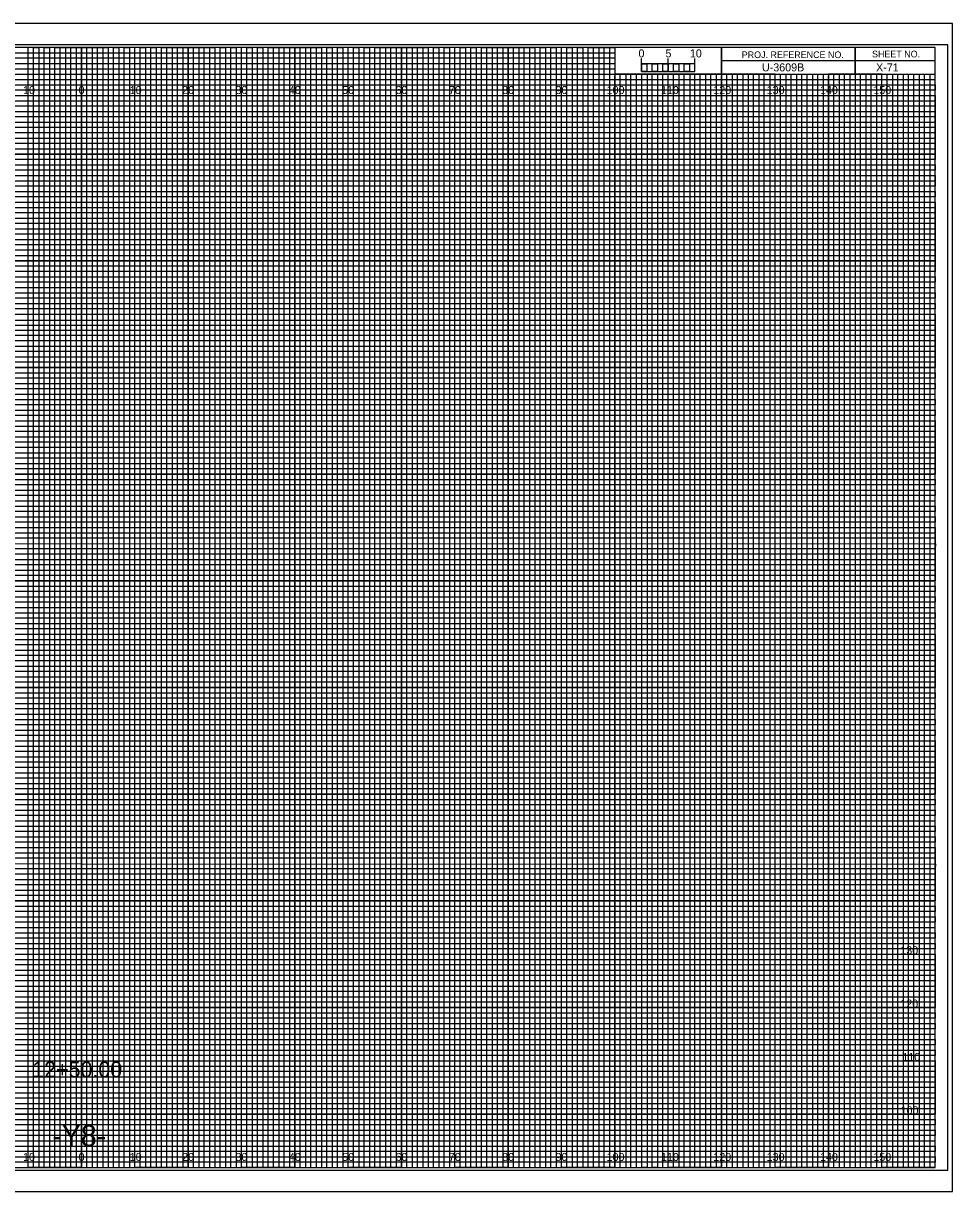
# Model space of a CAD drawing. Extents: x -13 to 323, y -5 to 434.
# Drawn here: x 149.1 to 323.3, y 215.5 to 434.5 of the extents above; entities that cross this region are included whole.
import ezdxf

# ---------------------------------------------------------------- set-up
doc = ezdxf.new("R2010")
doc.units = 0
for name, color, linetype in [('Exist CMT Pavement', 7, 'Continuous'), ('Exist Cross Section Cell', 7, 'Continuous'), ('Exist XS Center Line Elevation Label', 7, 'Continuous'), ('Exist XS Ground Line', 7, 'Continuous'), ('Prop CMT Pvmt Course 1 Wedge', 7, 'Continuous'), ('Prop CMT Pvmt Course 2', 7, 'Continuous'), ('Prop CMT Pvmt Course 2 Wedge', 7, 'Continuous'), ('Prop CMT Pvmt Course 3', 7, 'Continuous'), ('Prop CMT Pvmt Course 3 Wedge', 7, 'Continuous'), ('Prop CMT Pvmt Surface', 7, 'Continuous'), ('Prop CMT Pvmt Wedge Surface 1', 7, 'Continuous'), ('Prop CMT Pvmt Wedge Surface 2', 7, 'Continuous'), ('Prop CMT Shld Paved Course 1', 7, 'Continuous'), ('Prop CMT Shld Paved Course 2', 7, 'Continuous'), ('Prop CMT Shld Paved Course 3', 7, 'Continuous'), ('Prop CMT Subgrade Earthwork', 7, 'Continuous'), ('Scratch_Level_0', 7, 'Continuous')]:
    doc.layers.add(name, color=color, linetype=linetype)

msp = doc.modelspace()

# ---------------------------------------------------------------- linework, layer by layer
at = {"layer": 'Exist XS Center Line Elevation Label'}
for points in [[(145, 220), (155, 220), (155, 430), (165, 430), (165, 220), (175, 220), (175, 430), (185, 430), (185, 220), (195, 220), (195, 430), (205, 430), (205, 220), (215, 220), (215, 430), (225, 430), (225, 220), (235, 220), (235, 430), (245, 430), (245, 220), (255, 220), (255, 430), (259.93, 430), (260, 430), (260, 425), (264.99, 425), (264.99, 220), (275, 220), (275, 425), (285, 425), (285, 220), (295, 220), (295, 425), (305, 425), (305, 220), (315, 220), (315, 425)], [(0, 425), (275, 425)], [(0, 405), (320, 405), (320, 415), (0, 415)], [(0, 385), (320, 385), (320, 395), (0, 395)], [(0, 365), (320, 365), (320, 375), (0, 375)], [(0, 345), (320, 345), (320, 355), (0, 355)], [(0, 325), (320, 325), (320, 335), (0, 335)], [(0, 305), (320, 305), (320, 315), (0, 315)], [(0, 285), (320, 285), (320, 295), (0, 295)], [(0, 265), (320, 265), (320, 275), (0, 275)], [(0, 245), (320, 245), (320, 255), (0, 255)], [(0, 225), (320, 225), (320, 235), (0, 235)]]:
    msp.add_lwpolyline(points, dxfattribs=at)
at = {"layer": 'Exist XS Ground Line'}
for p, q in [((150, 430), (140, 430)), ((150, 220), (150, 430)), ((170, 430), (160, 430)), ((160, 430), (160, 220)), ((170, 220), (170, 430)), ((190, 430), (180, 430)), ((180, 430), (180, 220)), ((190, 220), (190, 430)), ((210, 430), (200, 430)), ((200, 430), (200, 220)), ((210, 220), (210, 430)), ((230, 430), (220, 430)), ((220, 430), (220, 220)), ((230, 220), (230, 430)), ((250, 430), (240, 430)), ((240, 430), (240, 220)), ((250, 220), (250, 430)), ((260, 430), (260, 220)), ((270, 220), (270, 425)), ((290, 425), (280, 425)), ((280, 425), (280, 220)), ((290, 220), (290, 425)), ((310, 425), (300, 425)), ((300, 425), (300, 220)), ((310, 220), (310, 425)), ((160, 220), (150, 220)), ((180, 220), (170, 220)), ((200, 220), (190, 220)), ((220, 220), (210, 220)), ((240, 220), (230, 220)), ((260, 220), (250, 220)), ((280, 220), (270, 220)), ((300, 220), (290, 220)), ((320, 220), (310, 220)), ((320, 220), (320, 220))]:
    msp.add_line(p, q, dxfattribs=at)
for points in [[(0, 420), (320, 420), (320, 410), (0, 410)], [(0, 400), (320, 400), (320, 390), (0, 390)], [(0, 380), (320, 380), (320, 370), (0, 370)], [(0, 360), (320, 360), (320, 350), (0, 350)], [(0, 340), (320, 340), (320, 330), (0, 330)], [(0, 320), (320, 320), (320, 310), (0, 310)], [(0, 300), (320, 300), (320, 290), (0, 290)], [(0, 280), (320, 280), (320, 270), (0, 270)], [(0, 260), (320, 260), (320, 250), (0, 250)], [(0, 240), (320, 240), (320, 230), (0, 230)]]:
    msp.add_lwpolyline(points, dxfattribs=at)
at = {"layer": 'Prop CMT Pvmt Course 1 Wedge'}
for p, q in [((323.3, 434.5), (-13.4, 434.5)), ((-13.4, 215.5), (323.3, 215.5))]:
    msp.add_line(p, q, dxfattribs=at)
at = {"layer": 'Prop CMT Pvmt Course 2'}
msp.add_lwpolyline([(-13.4, 215.5), (323.3, 215.5), (323.3, 434.5), (-13.4, 434.5)], close=True, dxfattribs=at)
at = {"layer": 'Prop CMT Pvmt Course 3'}
msp.add_lwpolyline([(-10.8, 219.5), (322.4, 219.5), (322.4, 430.5), (-10.8, 430.5)], close=True, dxfattribs=at)
at = {"layer": 'Prop CMT Shld Paved Course 1'}
for p, q in [((305, 430), (305, 425)), ((305, 425), (305, 430)), ((280, 427.5), (280, 425)), ((320, 427.49), (280, 427.49)), ((280, 425), (320, 425))]:
    msp.add_line(p, q, dxfattribs=at)
for points in [[(320, 430), (0, 430), (0, 220), (320, 220)], [(280, 430), (260, 430), (260, 425.03), (280, 425.03)], [(320, 430), (280, 430), (280, 425), (320, 425)]]:
    msp.add_lwpolyline(points, close=True, dxfattribs=at)
at = {"layer": 'Prop CMT Shld Paved Course 2'}
for p, q in [((267, 425), (266.01, 425)), ((266.01, 425), (266.01, 220)), ((267, 220), (267, 425)), ((269, 425), (268, 425)), ((268, 425), (268, 220)), ((269, 220), (269, 425)), ((266.01, 220), (265, 220)), ((268, 220), (267, 220))]:
    msp.add_line(p, q, dxfattribs=at)
for points in [[(150, 220), (151, 220), (151, 430), (152, 430), (152, 220)], [(152, 220), (153, 220), (153, 430), (154, 430), (154, 220)], [(155, 220), (156, 220), (156, 430), (157, 430), (157, 220)], [(157, 220), (158, 220), (158, 430), (159, 430), (159, 220)], [(160, 220), (161, 220), (161, 430), (162, 430), (162, 220)], [(162, 220), (163, 220), (163, 430), (164, 430), (164, 220)], [(165, 220), (166, 220), (166, 430), (167, 430), (167, 220)], [(167, 220), (168, 220), (168, 430), (169, 430), (169, 220)], [(170, 220), (171, 220), (171, 430), (172, 430), (172, 220)], [(172, 220), (173, 220), (173, 430), (174, 430), (174, 220)], [(175, 220), (176, 220), (176, 430), (177, 430), (177, 220)], [(177, 220), (178, 220), (178, 430), (179, 430), (179, 220)], [(180, 220), (181, 220), (181, 430), (182, 430), (182, 220)], [(182, 220), (183, 220), (183, 430), (184, 430), (184, 220)], [(185, 220), (186, 220), (186, 430), (187, 430), (187, 220)], [(187, 220), (188, 220), (188, 430), (189, 430), (189, 220)], [(190, 220), (191, 220), (191, 430), (192, 430), (192, 220)], [(192, 220), (193, 220), (193, 430), (194, 430), (194, 220)], [(195, 220), (196, 220), (196, 430), (197, 430), (197, 220)], [(197, 220), (198, 220), (198, 430), (199, 430), (199, 220)], [(200, 220), (201, 220), (201, 430), (202, 430), (202, 220)], [(202, 220), (203, 220), (203, 430), (204, 430), (204, 220)], [(205, 220), (206, 220), (206, 430), (207, 430), (207, 220)], [(207, 220), (208, 220), (208, 430), (209, 430), (209, 220)], [(210, 220), (211, 220), (211, 430), (212, 430), (212, 220)], [(212, 220), (213, 220), (213, 430), (214, 430), (214, 220)], [(215, 220), (216, 220), (216, 430), (217, 430), (217, 220)], [(217, 220), (218, 220), (218, 430), (219, 430), (219, 220)], [(220, 220), (221, 220), (221, 430), (222, 430), (222, 220)], [(222, 220), (223, 220), (223, 430), (224, 430), (224, 220)], [(225, 220), (226, 220), (226, 430), (227, 430), (227, 220)], [(227, 220), (228, 220), (228, 430), (229, 430), (229, 220)], [(230, 220), (231, 220), (231, 430), (232, 430), (232, 220)], [(232, 220), (233, 220), (233, 430), (234, 430), (234, 220)], [(235, 220), (236, 220), (236, 430), (237, 430), (237, 220)], [(237, 220), (238, 220), (238, 430), (239, 430), (239, 220)], [(240, 220), (241, 220), (241, 430), (242, 430), (242, 220)], [(242, 220), (243, 220), (243, 430), (244, 430), (244, 220)], [(245, 220), (246, 220), (246, 430), (247, 430), (247, 220)], [(247, 220), (248, 220), (248, 430), (249, 430), (249, 220)], [(250, 220), (251, 220), (251, 430), (252, 430), (252, 220)], [(252, 220), (253, 220), (253, 430), (254, 430), (254, 220)], [(255, 220), (256, 220), (256, 430), (257, 430), (257, 220)], [(257, 220), (258, 220), (258, 430), (259, 430), (259, 220)], [(260, 220), (261, 220), (261, 425), (262.02, 425), (262.02, 220)], [(262, 220), (263, 220), (263, 425), (263.99, 425), (263.99, 220)], [(270, 220), (270.98, 220), (270.98, 425), (272, 425), (272, 220)], [(272, 220), (273, 220), (273, 425), (274.05, 425), (274.05, 220)], [(275, 220), (276, 220), (276, 425), (277, 425), (277, 220)], [(277, 220), (278, 220), (278, 425), (279, 425), (279, 220)], [(280, 220), (281, 220), (281, 425), (282, 425), (282, 220)], [(282, 220), (283, 220), (283, 425), (284, 425), (284, 220)], [(285, 220), (286, 220), (286, 425), (287, 425), (287, 220)], [(287, 220), (288, 220), (288, 425), (289, 425), (289, 220)], [(290, 220), (291, 220), (291, 425), (292, 425), (292, 220)], [(292, 220), (293, 220), (293, 425), (294, 425), (294, 220)], [(295, 220), (296, 220), (296, 425), (297, 425), (297, 220)], [(297, 220), (298, 220), (298, 425), (299, 425), (299, 220)], [(300, 220), (301, 220), (301, 425), (302, 425), (302, 220)], [(302, 220), (303, 220), (303, 425), (304, 425), (304, 220)], [(305, 220), (306, 220), (306, 425), (307, 425), (307, 220)], [(307, 220), (308, 220), (308, 425), (309, 425), (309, 220)], [(310, 220), (311, 220), (311, 425), (312, 425), (312, 220)], [(312, 220), (313, 220), (313, 425), (314, 425), (314, 220)], [(315, 220), (316, 220), (316, 425), (317, 425), (317, 220)], [(317, 220), (318, 220), (318, 425), (319, 425), (319, 220)]]:
    msp.add_lwpolyline(points, dxfattribs=at)
at = {"layer": 'Prop CMT Shld Paved Course 3'}
for p, q in [((265, 425.49), (265, 427.9)), ((265, 426.9), (265, 427.9)), ((270, 425.49), (270, 427.9)), ((275, 425.49), (275, 427.9)), ((275, 426.9), (275, 427.9))]:
    msp.add_line(p, q, dxfattribs=at)
for points in [[(275, 426.9), (265, 426.9), (265, 425.49), (275, 425.49)], [(265, 426.9), (266, 426.9), (266, 425.49), (265, 425.49)], [(267, 426.9), (268, 426.9), (268, 425.49), (267, 425.49)], [(269, 426.9), (270, 426.9), (270, 425.49), (269, 425.49)], [(271, 426.9), (272, 426.9), (272, 425.49), (271, 425.49)], [(273, 426.9), (274, 426.9), (274, 425.49), (273, 425.49)]]:
    msp.add_lwpolyline(points, close=True, dxfattribs=at)
at = {"layer": 'Prop CMT Subgrade Earthwork'}
for p, q in [((150, 220), (150, 430)), ((160, 220), (160, 430)), ((170, 220), (170, 430)), ((180, 220), (180, 430)), ((190, 220), (190, 430)), ((200, 220), (200, 430)), ((210, 220), (210, 430)), ((220, 220), (220, 430)), ((230, 220), (230, 430)), ((240, 220), (240, 430)), ((250, 220), (250, 430)), ((260, 220), (260, 424.69)), ((270, 220), (270, 424.69)), ((280, 220), (280, 424.69)), ((290, 220), (290, 424.69)), ((300, 220), (300, 424.69)), ((310, 220), (310, 424.69)), ((0, 420), (320, 420)), ((0, 410), (320, 410)), ((0, 400), (320, 400)), ((0, 390), (320, 390)), ((0, 380), (320, 380)), ((0, 370), (320, 370)), ((0, 360), (320, 360)), ((0, 350), (320, 350)), ((0, 340), (320, 340)), ((0, 330), (320, 330)), ((0, 320), (320, 320)), ((0, 310), (320, 310)), ((0, 300), (320, 300)), ((0, 290), (320, 290)), ((0, 280), (320, 280)), ((0, 270), (320, 270)), ((0, 260), (320, 260)), ((0, 250), (320, 250)), ((0, 240), (320, 240)), ((0, 230), (320, 230))]:
    msp.add_line(p, q, dxfattribs=at)
at = {"layer": 'Scratch_Level_0'}
for p, q in [((0, 429), (260, 429)), ((260, 427.98), (0, 427.98)), ((260, 429), (260, 427.98)), ((0, 427), (260, 427)), ((260, 425.89), (0, 425.89)), ((260, 427), (260, 425.89)), ((0, 424), (320, 424))]:
    msp.add_line(p, q, dxfattribs=at)
for points in [[(0, 423), (270, 423), (320, 423), (320, 422), (0, 422)], [(0, 421), (320, 421), (320, 419), (0, 419)], [(0, 418), (320, 418), (320, 417), (0, 416.98)], [(0, 416), (320, 416), (320, 414), (0, 414)], [(0, 413), (320, 413), (320, 412), (0, 412)], [(0, 411), (320, 411), (320, 409), (0, 409)], [(0, 408), (320, 408), (320, 407), (0, 407)], [(0, 406), (320, 406), (320, 404), (0, 404)], [(0, 403), (320, 403), (320, 402), (0, 402)], [(0, 401), (320, 401), (320, 399), (0, 399)], [(0, 398), (320, 398), (320, 397), (0, 397)], [(0, 396), (320, 396), (320, 393.95), (320, 393), (320, 392), (0, 392)], [(0, 394), (320, 394), (320, 393), (0, 393)], [(0, 391), (320, 391), (320, 389), (0, 389.03)], [(0, 389.03), (320, 389), (320, 388), (0, 388)], [(0, 387), (320, 387), (320, 386), (0, 386)], [(0, 384), (320, 384), (320, 383), (0, 383)], [(0, 382), (320, 382), (320, 381), (0, 381)], [(-0.07, 378.89), (320, 378.89), (320, 377.88), (-0.07, 377.88)], [(0, 377), (320, 377), (320, 376), (0, 376)], [(0, 374), (320, 374), (320, 373), (0, 373)], [(0, 372), (320, 372), (320, 371), (0, 371)], [(0, 369), (320, 369), (320, 368), (0, 368)], [(0, 367), (320, 367), (320, 366), (0, 366)], [(0, 364), (320, 364), (320, 363), (0, 363)], [(0, 362), (320, 362), (320, 361), (0, 361)], [(0, 359), (320, 359), (319.99, 357.98), (0, 358)], [(0, 357), (320, 357), (320, 356), (0, 356)], [(0, 354), (320, 354), (320, 353), (0, 353)], [(0, 352), (320, 352), (320, 351), (0, 351)], [(0, 349), (320, 349), (320, 348), (0, 348)], [(0, 347), (320, 347), (320, 346), (0, 346)], [(0, 344), (320, 344), (320, 343), (0, 343)], [(0, 342), (320, 342), (320, 341), (0, 341)], [(0, 339), (320, 339), (320, 338), (0, 338)], [(0, 336.99), (320.07, 336.91), (320, 336), (0, 336)], [(0, 334), (320, 334), (320, 333), (0, 333)], [(0, 332), (320, 332), (320, 331), (0, 331)], [(0, 329), (320, 329), (320, 328), (0, 328)], [(0, 327), (320, 327), (320, 326), (0, 326)], [(0, 324), (320, 324), (320, 323), (0, 323)], [(0, 322), (320, 322), (320, 321), (0, 321)], [(0, 319), (320, 319), (320, 318), (0, 318)], [(0, 317), (320, 317), (320, 316), (0, 316)], [(0, 314), (320, 314), (320, 313), (0, 313)], [(0, 312), (320, 312), (320, 311), (0, 311)], [(0, 309), (320, 309), (320, 308), (0, 308)], [(0, 307), (320, 307), (320, 306), (0, 306)], [(0, 304), (320, 304), (320, 303), (0, 303)], [(0, 302), (320, 302), (320, 301), (0, 301)], [(0, 299), (320, 299), (319.99, 297.98), (0, 298)], [(0, 297), (320, 297), (320, 296), (0, 296)], [(0, 294), (320, 294), (320, 293), (0, 293)], [(0, 292), (320, 292), (320, 291), (0, 291)], [(0, 289), (320, 289), (320, 288), (0, 288)], [(0, 287), (320, 287), (320, 286), (0, 286)], [(0, 284), (320, 284), (320, 283), (0, 283)], [(0, 282), (320, 282), (320, 281), (0, 281)], [(0, 279), (320, 279), (320, 278), (0, 278)], [(0, 276.99), (320.07, 276.91), (320, 276), (0, 276)], [(0, 274), (320, 274), (320, 273), (0, 273)], [(0, 272), (320, 272), (320, 271), (0, 271)], [(0, 269), (320, 269), (320, 268), (0, 268)], [(0, 267), (320, 267), (320, 266), (0, 266)], [(0, 264), (320, 264), (320, 263), (0, 263)], [(0, 262), (320, 262), (320, 261), (0, 261)], [(0, 259), (320, 259), (320, 258), (0, 258)], [(0, 257), (320, 257), (320, 256), (0, 256)], [(0, 254), (320, 254), (320, 253), (0, 253)], [(0, 252), (320, 252), (320, 251), (0, 251)], [(0, 249), (320, 249), (320, 248), (0, 248)], [(0, 247), (320, 247), (320, 246), (0, 246)], [(0, 244), (320, 244), (320, 243), (0, 243)], [(0, 242), (320, 242), (320, 241), (0, 241)], [(0, 239), (320, 239), (320, 238), (0, 238)], [(0, 237), (320, 237), (320, 236), (0, 236)], [(0, 234), (320, 234), (320, 233), (0, 233)], [(0, 232), (320, 232), (320, 231), (0, 231)], [(0, 229), (320, 229), (320, 228), (0, 228)], [(0, 227), (320, 227), (320, 226), (0, 226)], [(0, 224), (320, 224), (320, 223), (0, 223)], [(0, 222), (320, 222), (320, 221), (0, 221)]]:
    msp.add_lwpolyline(points, dxfattribs=at)

# ---------------------------------------------------------------- texts
at = {"layer": 'Exist CMT Pavement'}
msp.add_text('X-71', height=1.5, dxfattribs=at).set_placement((308.95, 425.5))
at = {"layer": 'Exist Cross Section Cell'}
for s, p in [('10', (149.04, 421.25)), ('0', (159.45, 421.25)), ('0', (159.45, 421.25)), ('10', (169.04, 421.25)), ('20', (178.86, 421.25)), ('30', (188.86, 421.25)), ('40', (198.86, 421.25)), ('50', (208.86, 421.25)), ('60', (218.86, 421.25)), ('70', (228.86, 421.25)), ('80', (238.86, 421.25)), ('90', (248.86, 421.25)), ('100', (258.44, 421.25)), ('110', (268.62, 421.25)), ('120', (278.44, 421.25)), ('130', (288.44, 421.25)), ('140', (298.44, 421.25)), ('150', (308.44, 421.25)), ('10', (149.04, 221.25)), ('0', (159.45, 221.25)), ('0', (159.45, 221.25)), ('10', (169.04, 221.25)), ('20', (178.86, 221.25)), ('30', (188.86, 221.25)), ('40', (198.86, 221.25)), ('50', (208.86, 221.25)), ('60', (218.86, 221.25)), ('70', (228.86, 221.25)), ('80', (238.86, 221.25)), ('90', (248.86, 221.25)), ('100', (258.44, 221.25)), ('110', (268.62, 221.25)), ('120', (278.44, 221.25)), ('130', (288.44, 221.25)), ('140', (298.44, 221.25)), ('150', (308.44, 221.25))]:
    msp.add_text(s, height=1.5, dxfattribs=at).set_placement(p)
at = {"layer": 'Prop CMT Pvmt Course 2 Wedge'}
for s, p in [('130', (313.49, 260)), ('120', (313.5, 250)), ('110', (313.88, 240)), ('100', (313.55, 230))]:
    msp.add_text(s, height=1.5, dxfattribs=at).set_placement(p)
at = {"layer": 'Prop CMT Pvmt Course 3 Wedge'}
msp.add_text('12+50.00', height=3, dxfattribs=at).set_placement((150.77, 236.9))
at = {"layer": 'Prop CMT Pvmt Surface'}
msp.add_text('U-3609B', height=1.5, dxfattribs=at).set_placement((287.56, 425.5))
at = {"layer": 'Prop CMT Pvmt Wedge Surface 1'}
msp.add_text('-Y8-', height=4, dxfattribs=at).set_placement((154.52, 224))
at = {"layer": 'Prop CMT Pvmt Wedge Surface 2'}
for s, p in [('5', (269.47, 428.12)), ('10', (274.04, 428.12))]:
    msp.add_text(s, height=1.5, dxfattribs=at).set_placement(p)
at = {"layer": 'Prop CMT Shld Paved Course 1'}
for s, p in [('PROJ. REFERENCE NO.', (283.77, 427.99)), ('SHEET NO.', (308.19, 428.12))]:
    msp.add_text(s, height=1.25, dxfattribs=at).set_placement(p)
at = {"layer": 'Prop CMT Shld Paved Course 3'}
msp.add_text('0', height=1.5, dxfattribs=at).set_placement((264.41, 428.12))

doc.saveas('drawing.dxf')
